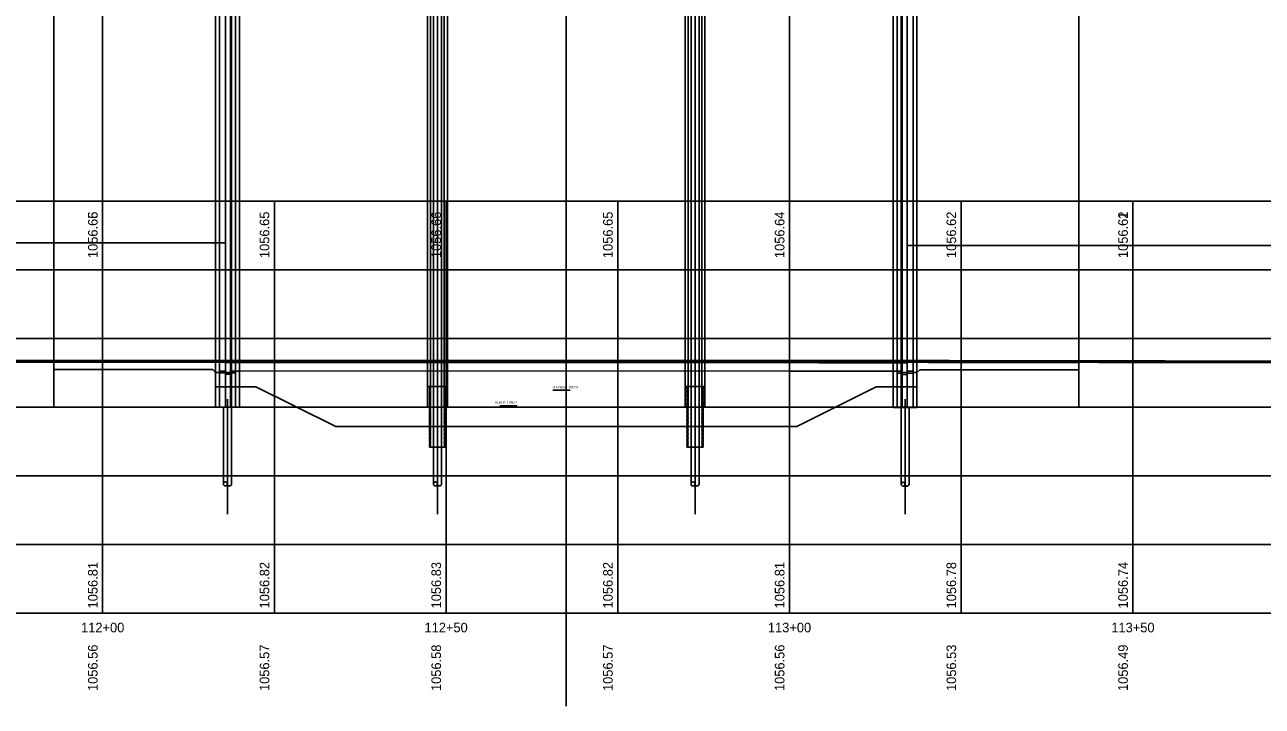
# Model space of a CAD drawing. Extents: x -1300 to 1299, y -770 to 1120.
# Drawn here: x 581.9 to 762.1, y -419.5 to -320.2 of the extents above; entities that cross this region are included whole.
import ezdxf

# ---------------------------------------------------------------- set-up
doc = ezdxf.new("R2010")
doc.units = 0
for name, color, linetype in [('BR_P_Gen_Joint_Filler', 7, 'Continuous'), ('BR_P_Slab_Object', 7, 'Continuous'), ('BR_X_Brg_Centerline', 7, 'Continuous'), ('BR_X_Gen_Approach_Slab', 7, 'Continuous'), ('BR_X_Slab_Object', 7, 'Continuous'), ('BR_X_Sub_Deep_Centerline', 7, 'Continuous'), ('BR_X_Sub_Deep_Object', 7, 'Continuous'), ('BR_X_Sub_Object', 7, 'Continuous'), ('PF_X_Ground_Line', 7, 'Continuous'), ('SC_Scratch1', 7, 'Continuous'), ('SC_Scratch2', 7, 'Continuous'), ('SC_Scratch3', 7, 'Continuous'), ('XS_P_Pavt_Surface', 7, 'Continuous')]:
    doc.layers.add(name, color=color, linetype=linetype)

msp = doc.modelspace()

# ---------------------------------------------------------------- linework, layer by layer
at = {"layer": 'BR_P_Gen_Joint_Filler'}
for points in [[(611.06, -369.23), (611.14, -369.23), (611.14, -369.4), (611.06, -369.4)], [(710.38, -369.26), (710.47, -369.26), (710.47, -369.43), (710.38, -369.43)]]:
    msp.add_lwpolyline(points, close=True, dxfattribs=at)
at = {"layer": 'BR_P_Slab_Object'}
for p, q in [((611.14, -369.42), (611.14, -369.28)), ((710.38, -369.3), (710.38, -369.45))]:
    msp.add_line(p, q, dxfattribs=at)
for points in [[(611.14, -369.23), (643.26, -369.22), (693.26, -369.24)], [(693.26, -369.43), (643.26, -369.41), (611.14, -369.42)]]:
    msp.add_lwpolyline(points, dxfattribs=at)
for centre in [(688.62, -11984.54), (688.62, -11984.73)]:
    msp.add_arc(centre, 11615.3, 89.892632, 89.977082, dxfattribs=at)
at = {"layer": 'BR_X_Brg_Centerline'}
for p, q in [((612.01, -368.52), (612.01, -371.62)), ((709.52, -368.54), (709.52, -371.65)), ((642.01, -369.8), (642.01, -391.5)), ((679.51, -369.81), (679.51, -391.5))]:
    msp.add_line(p, q, dxfattribs=at)
at = {"layer": 'BR_X_Gen_Approach_Slab'}
for p, q in [((611.14, -369.36), (593.26, -369.37)), ((586.14, -369.37), (586.14, -370.46)), ((593.26, -370.45), (609.29, -370.44)), ((609.29, -370.44), (609.7, -370.86)), ((609.7, -370.86), (610.28, -370.86)), ((735.38, -369.42), (735.38, -370.51))]:
    msp.add_line(p, q, dxfattribs=at)
msp.add_lwpolyline([(712.24, -370.47), (711.83, -370.88), (711.25, -370.88)], dxfattribs=at)
for centre, start, end in [((655.76, -62869.52), 90.0572958, 90.0638229), ((655.76, -62870.6), 90.0572958, 90.0638229), ((630.76, -62869.52), 89.9040915, 89.9270098), ((630.76, -62870.6), 89.9040915, 89.9253092)]:
    msp.add_arc(centre, 62500.19, start, end, dxfattribs=at)
at = {"layer": 'BR_X_Slab_Object'}
for p, q in [((611.14, -369.36), (611.14, -370.65)), ((710.38, -370.67), (710.38, -369.38))]:
    msp.add_line(p, q, dxfattribs=at)
for points in [[(693.26, -369.37), (643.26, -369.35), (611.14, -369.36)], [(613.17, -370.65), (643.26, -370.64), (693.26, -370.66)]]:
    msp.add_lwpolyline(points, dxfattribs=at)
for centre, start in [((630.76, -62869.52), 89.9270098), ((630.76, -62870.81), 89.9288623)]:
    msp.add_arc(centre, 62500.19, start, 89.9427042, dxfattribs=at)
at = {"layer": 'BR_X_Sub_Deep_Centerline'}
for p, q in [((611.43, -374.73), (611.43, -391.5)), ((710.1, -374.76), (710.1, -391.5))]:
    msp.add_line(p, q, dxfattribs=at)
at = {"layer": 'BR_X_Sub_Deep_Object'}
for p, q in [((641.43, -372.91), (641.43, -387.1)), ((642.6, -372.91), (642.6, -387.1)), ((678.93, -372.92), (678.93, -387.1)), ((680.1, -372.92), (680.1, -387.1)), ((610.85, -387.1), (610.85, -375.93)), ((612.02, -387.1), (612.02, -375.93)), ((709.52, -387.13), (709.52, -375.96)), ((710.68, -387.13), (710.68, -375.96))]:
    msp.add_line(p, q, dxfattribs=at)
for points in [[(640.94, -372.91), (641.01, -372.92), (641.01, -372.98), (640.83, -373.02), (640.83, -373.08), (641.01, -373.12), (641.01, -373.18), (640.83, -373.21), (640.83, -373.28), (641.01, -373.31), (641.01, -373.37), (640.83, -373.4), (640.83, -373.47), (641.01, -373.5), (641.01, -373.56), (640.83, -373.59), (640.83, -373.66), (641.01, -373.69), (641.01, -373.76), (640.83, -373.79), (640.83, -373.86), (641.01, -373.89), (641.01, -373.95), (640.83, -373.98), (640.83, -374.05), (641.01, -374.08), (641.01, -374.14), (640.83, -374.17), (640.83, -374.24), (641.01, -374.27), (641.01, -374.34), (640.83, -374.37), (640.83, -374.43), (641.01, -374.47), (641.01, -374.53), (640.83, -374.56), (640.83, -374.63), (641.01, -374.66), (641.01, -374.72), (640.83, -374.75), (640.83, -374.82), (641.01, -374.85), (641.01, -374.92), (640.83, -374.95), (640.83, -375.01), (641.01, -375.05), (641.01, -375.11), (640.83, -375.14), (640.83, -375.21), (641.01, -375.24), (641.01, -375.3), (640.83, -375.33), (640.83, -375.4), (641.01, -375.43), (641.01, -375.5), (640.83, -375.53), (640.83, -375.59), (641.01, -375.63), (641.01, -375.69), (640.83, -375.72), (640.83, -375.79), (641.01, -375.82), (641.01, -375.88), (640.83, -375.91), (640.83, -375.98), (641.01, -376.01), (641.01, -376.08), (640.83, -376.11), (640.83, -376.17), (641.01, -376.21), (641.01, -376.27), (640.83, -376.3), (640.83, -376.37), (641.01, -376.4), (641.01, -376.46), (640.83, -376.49), (640.83, -376.56), (641.01, -376.59), (641.01, -376.66), (640.83, -376.69), (640.83, -376.75), (641.01, -376.79), (641.01, -376.85), (640.83, -376.88), (640.83, -376.95), (641.01, -376.98), (641.01, -377.04), (640.83, -377.07), (640.83, -377.14), (641.01, -377.17), (641.01, -377.23), (640.83, -377.27), (640.83, -377.33), (641.01, -377.37), (641.01, -377.43), (640.83, -377.46), (640.83, -377.53), (641.01, -377.56), (641.01, -377.62), (640.83, -377.65), (640.83, -377.72), (641.01, -377.75), (641.01, -377.81), (640.83, -377.85), (640.83, -377.91), (641.01, -377.95), (641.01, -378.01), (640.83, -378.04), (640.83, -378.11), (641.01, -378.14), (641.01, -378.2), (640.83, -378.23), (640.83, -378.3), (641.01, -378.33), (641.01, -378.39), (640.83, -378.43), (640.83, -378.49), (641.01, -378.53), (641.01, -378.59), (640.83, -378.62), (640.83, -378.69), (641.01, -378.72), (641.01, -378.78), (640.83, -378.81), (640.83, -378.88), (641.01, -378.91), (641.01, -378.97), (640.83, -379.01), (640.83, -379.07), (641.01, -379.11), (641.01, -379.17), (640.83, -379.2), (640.83, -379.27), (641.01, -379.3), (641.01, -379.36), (640.83, -379.39), (640.83, -379.46), (641.01, -379.49), (641.01, -379.55), (640.83, -379.59), (640.83, -379.65), (641.01, -379.69), (641.01, -379.75), (640.83, -379.78), (640.83, -379.85), (641.01, -379.88), (641.01, -379.94), (640.83, -379.97), (640.83, -380.04), (641.01, -380.07), (641.01, -380.13), (640.83, -380.17), (640.83, -380.23), (641.01, -380.27), (641.01, -380.33), (640.83, -380.36), (640.83, -380.43), (641.01, -380.46), (641.01, -380.52), (640.83, -380.55), (640.83, -380.62), (641.01, -380.65), (641.01, -380.71), (640.83, -380.75), (640.83, -380.81), (641.01, -380.85), (641.01, -380.91), (640.83, -380.94), (640.83, -381.01), (641.01, -381.04), (641.01, -381.1), (640.83, -381.13), (640.83, -381.2), (641.01, -381.23), (641.01, -381.29), (640.83, -381.33), (640.83, -381.39), (641.01, -381.43), (641.01, -381.49), (640.83, -381.52), (640.83, -381.59), (641.01, -381.62), (641.01, -381.68), (640.83, -381.71), (640.83, -381.73), (643.2, -381.73), (643.2, -381.71), (643.01, -381.68), (643.01, -381.62), (643.2, -381.59), (643.2, -381.52), (643.01, -381.49), (643.01, -381.43), (643.2, -381.39), (643.2, -381.33), (643.01, -381.29), (643.01, -381.23), (643.2, -381.2), (643.2, -381.13), (643.01, -381.1), (643.01, -381.04), (643.2, -381.01), (643.2, -380.94), (643.01, -380.91), (643.01, -380.85), (643.2, -380.81), (643.2, -380.75), (643.01, -380.71), (643.01, -380.65), (643.2, -380.62), (643.2, -380.55), (643.01, -380.52), (643.01, -380.46), (643.2, -380.43), (643.2, -380.36), (643.01, -380.33), (643.01, -380.27), (643.2, -380.23), (643.2, -380.17), (643.01, -380.13), (643.01, -380.07), (643.2, -380.04), (643.2, -379.97), (643.01, -379.94), (643.01, -379.88), (643.2, -379.85), (643.2, -379.78), (643.01, -379.75), (643.01, -379.69), (643.2, -379.65), (643.2, -379.59), (643.01, -379.55), (643.01, -379.49), (643.2, -379.46), (643.2, -379.39), (643.01, -379.36), (643.01, -379.3), (643.2, -379.27), (643.2, -379.2), (643.01, -379.17), (643.01, -379.11), (643.2, -379.07), (643.2, -379.01), (643.01, -378.97), (643.01, -378.91), (643.2, -378.88), (643.2, -378.81), (643.01, -378.78), (643.01, -378.72), (643.2, -378.69), (643.2, -378.62), (643.01, -378.59), (643.01, -378.53), (643.2, -378.49), (643.2, -378.43), (643.01, -378.39), (643.01, -378.33), (643.2, -378.3), (643.2, -378.23), (643.01, -378.2), (643.01, -378.14), (643.2, -378.11), (643.2, -378.04), (643.01, -378.01), (643.01, -377.95), (643.2, -377.91), (643.2, -377.85), (643.01, -377.81), (643.01, -377.75), (643.2, -377.72), (643.2, -377.65), (643.01, -377.62), (643.01, -377.56), (643.2, -377.53), (643.2, -377.46), (643.01, -377.43), (643.01, -377.37), (643.2, -377.33), (643.2, -377.27), (643.01, -377.23), (643.01, -377.17), (643.2, -377.14), (643.2, -377.07), (643.01, -377.04), (643.01, -376.98), (643.2, -376.95), (643.2, -376.88), (643.01, -376.85), (643.01, -376.79), (643.2, -376.75), (643.2, -376.69), (643.01, -376.66), (643.01, -376.59), (643.2, -376.56), (643.2, -376.49), (643.01, -376.46), (643.01, -376.4), (643.2, -376.37), (643.2, -376.3), (643.01, -376.27), (643.01, -376.21), (643.2, -376.17), (643.2, -376.11), (643.01, -376.08), (643.01, -376.01), (643.2, -375.98), (643.2, -375.91), (643.01, -375.88), (643.01, -375.82), (643.2, -375.79), (643.2, -375.72), (643.01, -375.69), (643.01, -375.63), (643.2, -375.59), (643.2, -375.53), (643.01, -375.5), (643.01, -375.43), (643.2, -375.4), (643.2, -375.33), (643.01, -375.3), (643.01, -375.24), (643.2, -375.21), (643.2, -375.14), (643.01, -375.11), (643.01, -375.05), (643.2, -375.01), (643.2, -374.95), (643.01, -374.92), (643.01, -374.85), (643.2, -374.82), (643.2, -374.75), (643.01, -374.72), (643.01, -374.66), (643.2, -374.63), (643.2, -374.56), (643.01, -374.53), (643.01, -374.47), (643.2, -374.43), (643.2, -374.37), (643.01, -374.34), (643.01, -374.27), (643.2, -374.24), (643.2, -374.17), (643.01, -374.14), (643.01, -374.08), (643.2, -374.05), (643.2, -373.98), (643.01, -373.95), (643.01, -373.89), (643.2, -373.86), (643.2, -373.79), (643.01, -373.76), (643.01, -373.69), (643.2, -373.66), (643.2, -373.59), (643.01, -373.56), (643.01, -373.5), (643.2, -373.47), (643.2, -373.4), (643.01, -373.37), (643.01, -373.31), (643.2, -373.28), (643.2, -373.21), (643.01, -373.18), (643.01, -373.12), (643.2, -373.08), (643.2, -373.02), (643.01, -372.98), (643.01, -372.92), (643.09, -372.91)], [(678.51, -372.92), (678.51, -372.98), (678.33, -373.02), (678.33, -373.08), (678.51, -373.12), (678.51, -373.18), (678.33, -373.21), (678.33, -373.28), (678.51, -373.31), (678.51, -373.37), (678.33, -373.4), (678.33, -373.47), (678.51, -373.5), (678.51, -373.56), (678.33, -373.59), (678.33, -373.66), (678.51, -373.69), (678.51, -373.76), (678.33, -373.79), (678.33, -373.86), (678.51, -373.89), (678.51, -373.95), (678.33, -373.98), (678.33, -374.05), (678.51, -374.08), (678.51, -374.14), (678.33, -374.17), (678.33, -374.24), (678.51, -374.27), (678.51, -374.34), (678.33, -374.37), (678.33, -374.43), (678.51, -374.47), (678.51, -374.53), (678.33, -374.56), (678.33, -374.63), (678.51, -374.66), (678.51, -374.72), (678.33, -374.75), (678.33, -374.82), (678.51, -374.85), (678.51, -374.92), (678.33, -374.95), (678.33, -375.01), (678.51, -375.05), (678.51, -375.11), (678.33, -375.14), (678.33, -375.21), (678.51, -375.24), (678.51, -375.3), (678.33, -375.33), (678.33, -375.4), (678.51, -375.43), (678.51, -375.5), (678.33, -375.53), (678.33, -375.59), (678.51, -375.63), (678.51, -375.69), (678.33, -375.72), (678.33, -375.79), (678.51, -375.82), (678.51, -375.88), (678.33, -375.91), (678.33, -375.98), (678.51, -376.01), (678.51, -376.08), (678.33, -376.11), (678.33, -376.17), (678.51, -376.21), (678.51, -376.27), (678.33, -376.3), (678.33, -376.37), (678.51, -376.4), (678.51, -376.46), (678.33, -376.49), (678.33, -376.56), (678.51, -376.59), (678.51, -376.66), (678.33, -376.69), (678.33, -376.75), (678.51, -376.79), (678.51, -376.85), (678.33, -376.88), (678.33, -376.95), (678.51, -376.98), (678.51, -377.04), (678.33, -377.07), (678.33, -377.14), (678.51, -377.17), (678.51, -377.23), (678.33, -377.27), (678.33, -377.33), (678.51, -377.37), (678.51, -377.43), (678.33, -377.46), (678.33, -377.53), (678.51, -377.56), (678.51, -377.62), (678.33, -377.65), (678.33, -377.72), (678.51, -377.75), (678.51, -377.81), (678.33, -377.85), (678.33, -377.91), (678.51, -377.95), (678.51, -378.01), (678.33, -378.04), (678.33, -378.11), (678.51, -378.14), (678.51, -378.2), (678.33, -378.23), (678.33, -378.3), (678.51, -378.33), (678.51, -378.39), (678.33, -378.43), (678.33, -378.49), (678.51, -378.53), (678.51, -378.59), (678.33, -378.62), (678.33, -378.69), (678.51, -378.72), (678.51, -378.78), (678.33, -378.81), (678.33, -378.88), (678.51, -378.91), (678.51, -378.97), (678.33, -379.01), (678.33, -379.07), (678.51, -379.11), (678.51, -379.17), (678.33, -379.2), (678.33, -379.27), (678.51, -379.3), (678.51, -379.36), (678.33, -379.39), (678.33, -379.46), (678.51, -379.49), (678.51, -379.55), (678.33, -379.59), (678.33, -379.65), (678.51, -379.69), (678.51, -379.75), (678.33, -379.78), (678.33, -379.85), (678.51, -379.88), (678.51, -379.94), (678.33, -379.97), (678.33, -380.04), (678.51, -380.07), (678.51, -380.13), (678.33, -380.17), (678.33, -380.23), (678.51, -380.27), (678.51, -380.33), (678.33, -380.36), (678.33, -380.43), (678.51, -380.46), (678.51, -380.52), (678.33, -380.55), (678.33, -380.62), (678.51, -380.65), (678.51, -380.71), (678.33, -380.75), (678.33, -380.81), (678.51, -380.85), (678.51, -380.91), (678.33, -380.94), (678.33, -381.01), (678.51, -381.04), (678.51, -381.1), (678.33, -381.13), (678.33, -381.2), (678.51, -381.23), (678.51, -381.29), (678.33, -381.33), (678.33, -381.39), (678.51, -381.43), (678.51, -381.49), (678.33, -381.52), (678.33, -381.59), (678.51, -381.62), (678.51, -381.68), (678.33, -381.71), (678.33, -381.73), (680.7, -381.73), (680.7, -381.71), (680.51, -381.68), (680.51, -381.62), (680.7, -381.59), (680.7, -381.52), (680.51, -381.49), (680.51, -381.43), (680.7, -381.39), (680.7, -381.33), (680.51, -381.29), (680.51, -381.23), (680.7, -381.2), (680.7, -381.13), (680.51, -381.1), (680.51, -381.04), (680.7, -381.01), (680.7, -380.94), (680.51, -380.91), (680.51, -380.85), (680.7, -380.81), (680.7, -380.75), (680.51, -380.71), (680.51, -380.65), (680.7, -380.62), (680.7, -380.55), (680.51, -380.52), (680.51, -380.46), (680.7, -380.43), (680.7, -380.36), (680.51, -380.33), (680.51, -380.27), (680.7, -380.23), (680.7, -380.17), (680.51, -380.13), (680.51, -380.07), (680.7, -380.04), (680.7, -379.97), (680.51, -379.94), (680.51, -379.88), (680.7, -379.85), (680.7, -379.78), (680.51, -379.75), (680.51, -379.69), (680.7, -379.65), (680.7, -379.59), (680.51, -379.55), (680.51, -379.49), (680.7, -379.46), (680.7, -379.39), (680.51, -379.36), (680.51, -379.3), (680.7, -379.27), (680.7, -379.2), (680.51, -379.17), (680.51, -379.11), (680.7, -379.07), (680.7, -379.01), (680.51, -378.97), (680.51, -378.91), (680.7, -378.88), (680.7, -378.81), (680.51, -378.78), (680.51, -378.72), (680.7, -378.69), (680.7, -378.62), (680.51, -378.59), (680.51, -378.53), (680.7, -378.49), (680.7, -378.43), (680.51, -378.39), (680.51, -378.33), (680.7, -378.3), (680.7, -378.23), (680.51, -378.2), (680.51, -378.14), (680.7, -378.11), (680.7, -378.04), (680.51, -378.01), (680.51, -377.95), (680.7, -377.91), (680.7, -377.85), (680.51, -377.81), (680.51, -377.75), (680.7, -377.72), (680.7, -377.65), (680.51, -377.62), (680.51, -377.56), (680.7, -377.53), (680.7, -377.46), (680.51, -377.43), (680.51, -377.37), (680.7, -377.33), (680.7, -377.27), (680.51, -377.23), (680.51, -377.17), (680.7, -377.14), (680.7, -377.07), (680.51, -377.04), (680.51, -376.98), (680.7, -376.95), (680.7, -376.88), (680.51, -376.85), (680.51, -376.79), (680.7, -376.75), (680.7, -376.69), (680.51, -376.66), (680.51, -376.59), (680.7, -376.56), (680.7, -376.49), (680.51, -376.46), (680.51, -376.4), (680.7, -376.37), (680.7, -376.3), (680.51, -376.27), (680.51, -376.21), (680.7, -376.17), (680.7, -376.11), (680.51, -376.08), (680.51, -376.01), (680.7, -375.98), (680.7, -375.91), (680.51, -375.88), (680.51, -375.82), (680.7, -375.79), (680.7, -375.72), (680.51, -375.69), (680.51, -375.63), (680.7, -375.59), (680.7, -375.53), (680.51, -375.5), (680.51, -375.43), (680.7, -375.4), (680.7, -375.33), (680.51, -375.3), (680.51, -375.24), (680.7, -375.21), (680.7, -375.14), (680.51, -375.11), (680.51, -375.05), (680.7, -375.01), (680.7, -374.95), (680.51, -374.92), (680.51, -374.85), (680.7, -374.82), (680.7, -374.75), (680.51, -374.72), (680.51, -374.66), (680.7, -374.63), (680.7, -374.56), (680.51, -374.53), (680.51, -374.47), (680.7, -374.43), (680.7, -374.37), (680.51, -374.34), (680.51, -374.27), (680.7, -374.24), (680.7, -374.17), (680.51, -374.14), (680.51, -374.08), (680.7, -374.05), (680.7, -373.98), (680.51, -373.95), (680.51, -373.89), (680.7, -373.86), (680.7, -373.79), (680.51, -373.76), (680.51, -373.69), (680.7, -373.66), (680.7, -373.59), (680.51, -373.56), (680.51, -373.5), (680.7, -373.47), (680.7, -373.4), (680.51, -373.37), (680.51, -373.31), (680.7, -373.28), (680.7, -373.21), (680.51, -373.18), (680.51, -373.12), (680.7, -373.08), (680.7, -373.02), (680.51, -372.98), (680.51, -372.92)]]:
    msp.add_lwpolyline(points, dxfattribs=at)
for centre, radius in [((611.14, -387.1), 0.29), ((641.72, -387.1), 0.292), ((679.22, -387.1), 0.292), ((709.81, -387.13), 0.29)]:
    msp.add_circle(centre, radius, dxfattribs=at)
for centre, radius in [((611.73, -387.1), 0.293), ((642.31, -387.1), 0.292), ((679.81, -387.1), 0.292), ((710.39, -387.13), 0.293)]:
    msp.add_arc(centre, radius, 180, 0, dxfattribs=at)
at = {"layer": 'BR_X_Sub_Object'}
for p, q in [((610.28, -372.93), (610.28, -370.65)), ((610.28, -370.65), (611.14, -370.65)), ((611.14, -370.65), (611.14, -370.86)), ((611.14, -370.86), (611.87, -370.86)), ((612.59, -370.65), (613.17, -370.65)), ((612.59, -370.65), (612.59, -372.93)), ((613.17, -370.65), (613.17, -372.93)), ((609.7, -375.93), (609.7, -372.93)), ((609.7, -372.93), (613.17, -372.93)), ((613.17, -372.93), (613.17, -375.93)), ((708.36, -375.96), (708.36, -372.96)), ((708.36, -372.96), (711.83, -372.96)), ((711.83, -372.96), (711.83, -375.96)), ((613.17, -375.93), (609.7, -375.93)), ((711.83, -375.96), (708.36, -375.96)), ((711.83, -375.96), (708.36, -375.96)), ((711.83, -375.93), (711.83, -375.96))]:
    msp.add_line(p, q, dxfattribs=at)
for points in [[(611.87, -370.86), (611.87, -370.65), (612.59, -370.65)], [(640.57, -370.64), (640.57, -372.91), (643.46, -372.91), (643.46, -370.64)], [(678.07, -370.65), (678.07, -372.92), (680.96, -372.92), (680.96, -370.65)], [(708.94, -370.67), (708.36, -370.67), (708.36, -372.96)], [(708.94, -372.96), (708.94, -370.67), (709.66, -370.67), (709.66, -370.88), (710.38, -370.88), (710.38, -370.67), (711.25, -370.67), (711.25, -372.96)]]:
    msp.add_lwpolyline(points, dxfattribs=at)
at = {"layer": 'PF_X_Ground_Line'}
for p, q in [((613.17, -372.93), (615.59, -372.93)), ((615.59, -372.93), (627.19, -378.73)), ((694.34, -378.73), (705.88, -372.96)), ((705.88, -372.96), (708.36, -372.96)), ((627.19, -378.73), (694.34, -378.73))]:
    msp.add_line(p, q, dxfattribs=at)
msp.add_lwpolyline([(593.26, -369.12), (643.26, -369.1), (693.26, -369.12)], dxfattribs=at)
for centre, radius, start, end in [((655.76, -62869.27), 62500.19, 90.0638229, 90.1031323), ((595.43, -5788.02), 5418.9, 90.02292, 90.0982), ((688.62, -11984.41), 11615.3, 89.892632, 89.977082), ((630.76, -62869.27), 62500.19, 89.8968677, 89.9270098), ((630.76, -62869.54), 62500.46, 89.8510313, 89.8968677)]:
    msp.add_arc(centre, radius, start, end, dxfattribs=at)
at = {"layer": 'SC_Scratch1'}
for p, q in [((660.76, 424.91), (660.76, -419.48)), ((293.26, -345.93), (1018.26, -345.93)), ((593.26, -405.93), (593.26, -345.93)), ((618.26, -405.93), (618.26, -345.93)), ((643.26, -405.93), (643.26, -345.93)), ((668.26, -405.93), (668.26, -345.93)), ((693.26, -405.93), (693.26, -345.93)), ((718.26, -405.93), (718.26, -345.93)), ((743.26, -405.93), (743.26, -345.93)), ((293.26, -355.93), (1018.26, -355.93)), ((293.26, -365.93), (1018.26, -365.93)), ((293.26, -375.93), (1018.26, -375.93)), ((293.26, -385.93), (1018.26, -385.93)), ((293.26, -395.93), (1018.26, -395.93)), ((293.26, -405.93), (1018.26, -405.93))]:
    msp.add_line(p, q, dxfattribs=at)
for points in [[(610.28, -370.92), (611.14, -370.92), (611.14, -371.13), (611.87, -371.13), (611.87, -370.92), (612.59, -370.92)], [(711.25, -370.95), (710.38, -370.95), (710.38, -371.15), (709.66, -371.15), (709.66, -370.95), (708.94, -370.95)]]:
    msp.add_lwpolyline(points, dxfattribs=at)
at = {"layer": 'SC_Scratch2'}
for p, q in [((586.14, 424.91), (586.14, -375.93)), ((593.26, 424.91), (593.26, -375.93)), ((609.7, 424.91), (609.7, -375.93)), ((610.28, 424.91), (610.28, -375.93)), ((611.14, 424.91), (611.14, -375.93)), ((611.87, 424.91), (611.87, -375.93)), ((612.01, 424.91), (612.01, -375.93)), ((612.59, 424.91), (612.59, -375.93)), ((613.17, 424.91), (613.17, -375.93)), ((640.57, 424.91), (640.57, -375.93)), ((641.01, 424.91), (641.01, -375.93)), ((641.43, 424.91), (641.43, -375.93)), ((642.01, 424.91), (642.01, -375.93)), ((642.6, 424.91), (642.6, -375.93)), ((643.01, 424.91), (643.01, -375.93)), ((643.46, 424.91), (643.46, -375.93)), ((660.76, 424.91), (660.76, -375.93)), ((678.07, 424.91), (678.07, -375.93)), ((678.51, 424.91), (678.51, -375.93)), ((678.93, 424.91), (678.93, -375.93)), ((679.51, 424.91), (679.51, -375.93)), ((680.1, 424.91), (680.1, -375.93)), ((680.51, 424.91), (680.51, -375.93)), ((680.96, 424.91), (680.96, -375.93)), ((693.26, 424.91), (693.26, -375.93)), ((708.36, 424.91), (708.36, -375.93)), ((708.94, 424.91), (708.94, -375.93)), ((709.52, 424.91), (709.52, -375.93)), ((709.66, 424.91), (709.66, -375.93)), ((710.38, 424.91), (710.38, -375.93)), ((711.25, 424.91), (711.25, -375.93)), ((711.83, 424.91), (711.83, -375.93)), ((735.38, 424.91), (735.38, -375.93))]:
    msp.add_line(p, q, dxfattribs=at)
at = {"layer": 'SC_Scratch3'}
for p, q in [((511.14, -351.98), (611.14, -351.98)), ((561.14, -351.98), (611.14, -351.98)), ((611.14, -369.28), (611.14, -351.98)), ((710.38, -369.3), (710.38, -352.36)), ((710.38, -352.36), (760.38, -352.36)), ((710.38, -352.36), (810.38, -352.36)), ((660.76, -369.35), (660.76, -370.64)), ((658.81, -373.43), (661.31, -373.43)), ((651.11, -375.72), (653.61, -375.72))]:
    msp.add_line(p, q, dxfattribs=at)
at = {"layer": 'XS_P_Pavt_Surface'}
for p, q in [((611.14, -369.23), (473.64, -369.36)), ((611.14, -369.36), (473.64, -369.48)), ((710.38, -369.26), (847.88, -369.47)), ((710.38, -369.38), (847.88, -369.6))]:
    msp.add_line(p, q, dxfattribs=at)

# ---------------------------------------------------------------- texts
at = {"layer": 'SC_Scratch1'}
for s, p in [('1056.65', (592.53, -354.2)), ('1056.66', (592.53, -354.2)), ('1056.65', (617.53, -354.2)), ('1056.65', (617.53, -354.2)), ('1056.66', (642.53, -354.2)), ('1056.66', (642.53, -354.2)), ('1056.65', (667.53, -354.2)), ('1056.65', (667.53, -354.2)), ('1056.64', (692.53, -354.2)), ('1056.64', (692.53, -354.2)), ('1056.62', (717.53, -354.2)), ('1056.62', (717.53, -354.2)), ('1056.62', (742.53, -354.2)), ('1056.61', (742.53, -354.2)), ('1056.81', (592.53, -405.23)), ('1056.82', (617.53, -405.23)), ('1056.83', (642.53, -405.23)), ('1056.82', (667.53, -405.23)), ('1056.81', (692.53, -405.23)), ('1056.78', (717.53, -405.23)), ('1056.74', (742.53, -405.23)), ('1056.56', (592.53, -417.26)), ('1056.57', (617.53, -417.26)), ('1056.58', (642.53, -417.26)), ('1056.57', (667.53, -417.26)), ('1056.56', (692.53, -417.26)), ('1056.53', (717.53, -417.26)), ('1056.49', (742.53, -417.26))]:
    msp.add_text(s, height=1.4, rotation=90, dxfattribs=at).set_placement(p)
for s, p in [('112+00', (590.12, -408.71)), ('112+50', (640.12, -408.71)), ('113+00', (690.12, -408.71)), ('113+50', (740.12, -408.71))]:
    msp.add_text(s, height=1.4, dxfattribs=at).set_placement(p)
at = {"layer": 'SC_Scratch3'}
for s, p in [('O.H.W.M. 1052.5', (658.78, -373.19)), ('N.W.E. 1050.2', (650.47, -375.42))]:
    msp.add_text(s, height=0.35, dxfattribs=at).set_placement(p)

doc.saveas('drawing.dxf')
